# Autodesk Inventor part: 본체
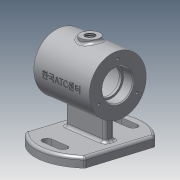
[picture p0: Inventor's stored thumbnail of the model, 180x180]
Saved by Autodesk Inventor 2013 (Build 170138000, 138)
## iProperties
Created: 2021-09
Part Number: 본체
Material: 알루미늄 6061
Document SubType Name: Modeling
Designer: kum
Density: 2.71 g/cm^3
Mass: 469.97 g
Surface Area: 487.044 cm^2
Volume: 173.421 cm^3
Author: kum
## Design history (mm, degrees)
sketch "스케치1"
  geometry: L1 (37.5, -36.742)-(37.5, 36.742); L2 (-37.5, -36.742)-(-37.5, 36.742); A1 r 52.5 centre (0, 0) between (-37.5, -36.742) and (37.5, -36.742); A2 r 52.5 centre (0, 0) between (37.5, 36.742) and (-37.5, 36.742); 1 further point
  constraints: 4 end point, 4 point on circle, 2 centre point, 1 coincident, 1 parallel, 1 vertical
  dimensions: "d8" = 37.5 distance from line of A1.centre L1; "d9" = 37.5 distance from line of point (0, 0) L2; "d10" = 52.5 radius of A1; "d11" = 52.5 radius of A2
extrude "돌출1" new body sketch "스케치1" distance "d5" = 10; taper "d6" = 0 deg
sketch "스케치5"
  geometry: L1 (0, 36.742)-(0, -36.742) reference; C1 r 30 at (62, 0); 2 further points
  constraints: 1 centre point, 1 horizontal alignment, 1 midpoint
  dimensions: "d20" = 60 diameter of C1; "d22" = 62 distance of point (0, 0) C1.centre
extrude "돌출4" join sketch "스케치5" stored distance "d23" = 70; taper "d24" = 0 deg
sketch "스케치6"
  geometry: L1 (-25, -5)-(25, -5); L2 (25, -5)-(25, 5); L3 (25, 5)-(-25, 5); L4 (-25, 5)-(-25, -5); L5 (-25, -5)-(25, 5); L6 (25, -5)-(-25, 5); A1 r 52.5 centre (0, 0) between (37.5, 36.742) and (-37.5, 36.742) reference
  constraints: 12 end point, 2 midpoint, 2 parallel, 1 horizontal, 1 perpendicular
  dimensions: "d25" = 50 distance of L3.end L2.end; "d26" = 10 distance of L2.end L1.end
extrude "돌출5" join sketch "스케치6" stored distance "d27" = 70; taper "d28" = 0 deg
sketch "스케치7"
  geometry: L1 (-35, 92)-(-35, 32) reference; L2 (35, 32)-(35, 92) reference; L3 (-35, 62)-(35, 62); L4 (-35, 62)-(-35, 78); L5 (-35, 78)-(-23, 78); L6 (-23, 78)-(-23, 76); L7 (-23, 76)-(-20, 76); L8 (-20, 76)-(-20, 87); L9 (-20, 87)-(20, 87); L10 (20, 87)-(20, 76); L11 (20, 76)-(23, 76); L12 (23, 76)-(23, 78); L13 (23, 78)-(35, 78); L14 (35, 78)-(35, 62); 1 further point
  constraints: 24 end point, 6 parallel, 3 perpendicular, 2 midpoint, 2 point on line, 1 collinear
  dimensions: "d29" = 32 diameter of L5 L3; "d31" = 28 diameter of L7 L3; "d32" = 50 diameter of L9 L3; "d33" = 28 diameter of L11 L3; "d34" = 32 diameter of L13 L3; "d35" = 12 distance between parallel lines of L2 L12; "d36" = 40 distance between parallel lines of L10 L8; "d37" = 12 distance between parallel lines of L6 L4; "d38" = 3 distance between parallel lines of L6 L8
revolve "회전1" sketch "스케치7" stored, may be unused: angle "d39" = 90 deg
node "작업 평면1"
sketch "스케치8"
  geometry: C1 r 10 at (0, 0); 1 further point
  constraints: 1 centre point, 1 coincident
  dimensions: "d41" = 20 diameter of C1
extrude "돌출6" join sketch "스케치8" stored distance "d42" = 70; taper "d43" = 0 deg
sketch "스케치9"
  geometry: C1 r 10 at (0, 0) reference; 1 further point
  constraints: 1 coincident
hole "구멍1" sketch "스케치9" at (0, 0) diameter "d44" = 10.106; stored, may be unused: countersink angle "d48" = 90 deg, drill point angle "d50" = 118 deg; dims "d45" = 28, "d46" = 4, "d47" = 2, "d49" = 30
sketch "스케치10"
  geometry: L1 (0, 23)-(0, 0); L2 (-19.919, -11.5)-(0, 0); L3 (19.919, -11.5)-(0, 0); C1 r 16 at (0, 0) reference; C2 r 30 at (0, 0) reference; A1 r 23 centre (0, 0) between (0, 23) and (19.919, -11.5); 1 further point
  constraints: 6 end point, 3 point on circle, 1 centre point, 1 coincident, 1 vertical, 1 vertical alignment
  dimensions: "d51" = 46 diameter of A1; "d67" = 120 deg angle of L3 L1; "d69" = 120 deg angle of L2 L3
hole "구멍2" sketch "스케치10" at (0, 23), (-19.919, -11.5), (19.919, -11.5) diameter "d52" = 3.242; stored, may be unused: countersink angle "d56" = 90 deg, drill point angle "d58" = 118 deg; dims "d53" = 8, "d54" = 4, "d55" = 2, "d57" = 10
sketch "스케치11"
  geometry: L1 (25, 5)-(25, -5) reference; L2 (-10, -32)-(10, -32); L3 (10, -42)-(-10, -42); A1 r 52.5 centre (0, 0) between (-37.5, -36.742) and (37.5, -36.742) reference; A2 r 5 centre (-10, -37) between (-10, -32) and (-10, -42); A3 r 5 centre (10, -37) between (10, -42) and (10, -32); 1 further point
  constraints: 4 end point, 4 point on circle, 3 tangent, 2 centre point, 1 horizontal alignment, 1 perpendicular, 1 vertical alignment
  dimensions: "d59" = 10 diameter of A3; "d60" = 10 diameter of A2; "d61" = 20 distance of A3.centre A2.centre; "d62" = 37 vertical distance of A2.centre A1.centre; "d63" = 10 distance of A3.centre point (0, -37); "d64" = 10 distance of point (0, -37) A2.centre
extrude "돌출7" cut sketch "스케치11" stored distance "d65" = 70; taper "d66" = 0 deg
fillet "모깎기1" dims "d71" = 0.3
fillet "모깎기2" dims "d72" = 3
chamfer "모따기1" distance "d73" = 1; stored, may be unused: second distance "d74" = 2, angle "d75" = 45 deg
node "작업 평면2"
sketch "스케치12"
  geometry: L1 (-35, 92)-(-35, 32) reference; L2 (-35, 92)-(35, 92) reference; 2 further points
  constraints: 1 other
  dimensions: "d77" = 35 distance from line of L1 point (0, 62); "d78" = 30 distance from line of L2 point (0, 62)
feature "엠보싱1" sketch "스케치12" dims "d7" = 105, "d26" = 10, "d79" = 0.5, "d80" = 0
node "솔리드1"
mirror "대칭1"
mirror "대칭2"
other parameters: "d0" = 105, "d40" = 95
